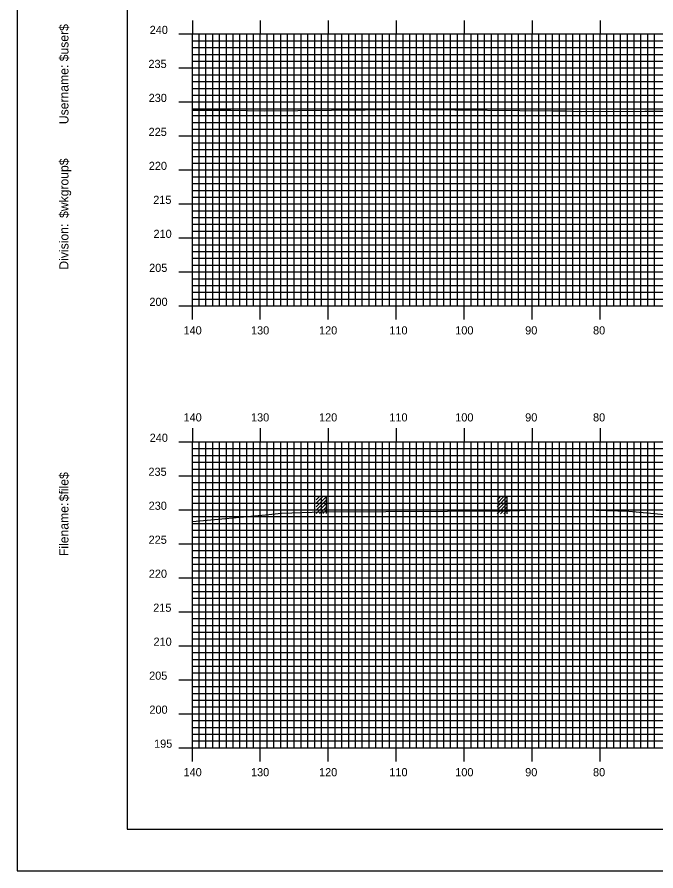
# Model space of a CAD drawing. Extents: x 1801536 to 1801879, y 442591 to 442811.
# Drawn here: x 1801535.8 to 1801629.8, y 442590.5 to 442716.2 of the extents above; entities that cross this region are included whole.
import ezdxf

# ---------------------------------------------------------------- set-up
doc = ezdxf.new("R2010")
doc.units = 0
for name, color, linetype in [('BORDER', 7, 'Continuous'), ('H_V ANNOTATION', 7, 'Continuous'), ('M_Buildings_Rooftop', 7, 'Continuous'), ('MAJOR', 7, 'Continuous'), ('MINOR', 7, 'Continuous'), ('PLOT BOUNDARY', 7, 'Continuous'), ('S_Roadway_Centerline', 7, 'Continuous')]:
    doc.layers.add(name, color=color, linetype=linetype)

msp = doc.modelspace()

# ---------------------------------------------------------------- linework, layer by layer
at = {"layer": 'BORDER'}
msp.add_lwpolyline([(1801551.98, 442596.67), (1801871.98, 442596.67), (1801871.98, 442806.67), (1801551.98, 442806.67)], close=True, dxfattribs=at)
at = {"layer": 'M_Buildings_Rooftop'}
for p, q in [((1801579.81, 442644.13), (1801581.32, 442645.64)), ((1801579.81, 442644.63), (1801580.8, 442645.64)), ((1801579.81, 442645.12), (1801580.3, 442645.64)), ((1801579.81, 442643.64), (1801581.32, 442645.12)), ((1801579.81, 442643.12), (1801581.32, 442644.63)), ((1801581.32, 442643.12), (1801581.32, 442645.64)), ((1801606.41, 442644.1), (1801607.92, 442645.61)), ((1801606.41, 442644.59), (1801607.4, 442645.61)), ((1801606.41, 442645.09), (1801606.91, 442645.61)), ((1801606.41, 442643.61), (1801607.92, 442645.09)), ((1801606.41, 442643.09), (1801607.92, 442644.59)), ((1801607.92, 442643.09), (1801607.92, 442645.61)), ((1801580.3, 442643.12), (1801581.32, 442644.13)), ((1801580.8, 442643.12), (1801581.32, 442643.64)), ((1801606.91, 442643.09), (1801607.92, 442644.1)), ((1801607.4, 442643.09), (1801607.92, 442643.61))]:
    msp.add_line(p, q, dxfattribs=at)
at = {"layer": 'MAJOR'}
for p, q in [((1801561.58, 442715.67), (1801561.58, 442713.67)), ((1801571.58, 442715.67), (1801571.58, 442713.67)), ((1801581.58, 442715.67), (1801581.58, 442713.67)), ((1801591.58, 442715.67), (1801591.58, 442713.67)), ((1801601.58, 442715.67), (1801601.58, 442713.67)), ((1801611.58, 442715.67), (1801611.58, 442713.67)), ((1801621.58, 442715.67), (1801621.58, 442713.67)), ((1801559.57, 442713.67), (1801561.58, 442713.67)), ((1801561.58, 442713.67), (1801841.58, 442713.67)), ((1801561.58, 442673.67), (1801561.58, 442713.67)), ((1801561.58, 442673.67), (1801561.58, 442713.67)), ((1801561.58, 442713.67), (1801841.58, 442713.67)), ((1801571.58, 442673.67), (1801571.58, 442713.67)), ((1801581.58, 442673.67), (1801581.58, 442713.67)), ((1801591.58, 442673.67), (1801591.58, 442713.67)), ((1801601.58, 442673.67), (1801601.58, 442713.67)), ((1801611.58, 442673.67), (1801611.58, 442713.67)), ((1801621.58, 442673.67), (1801621.58, 442713.67)), ((1801559.57, 442708.67), (1801561.58, 442708.67)), ((1801561.58, 442708.67), (1801841.58, 442708.67)), ((1801559.57, 442703.67), (1801561.58, 442703.67)), ((1801561.58, 442703.67), (1801841.58, 442703.67)), ((1801559.57, 442698.67), (1801561.58, 442698.67)), ((1801561.58, 442698.67), (1801841.58, 442698.67)), ((1801559.57, 442693.67), (1801561.58, 442693.67)), ((1801561.58, 442693.67), (1801841.58, 442693.67)), ((1801559.57, 442688.67), (1801561.58, 442688.67)), ((1801561.58, 442688.67), (1801841.58, 442688.67)), ((1801559.57, 442683.67), (1801561.58, 442683.67)), ((1801561.58, 442683.67), (1801841.58, 442683.67)), ((1801559.57, 442678.67), (1801561.58, 442678.67)), ((1801561.58, 442678.67), (1801841.58, 442678.67)), ((1801559.57, 442673.67), (1801561.58, 442673.67)), ((1801561.58, 442673.67), (1801841.58, 442673.67)), ((1801561.58, 442673.67), (1801841.58, 442673.67)), ((1801561.58, 442671.66), (1801561.58, 442673.67)), ((1801571.58, 442671.66), (1801571.58, 442673.67)), ((1801581.58, 442671.66), (1801581.58, 442673.67)), ((1801591.58, 442671.66), (1801591.58, 442673.67)), ((1801601.58, 442671.66), (1801601.58, 442673.67)), ((1801611.58, 442671.66), (1801611.58, 442673.67)), ((1801621.58, 442671.66), (1801621.58, 442673.67)), ((1801561.58, 442655.67), (1801561.58, 442653.67)), ((1801571.58, 442655.67), (1801571.58, 442653.67)), ((1801581.58, 442655.67), (1801581.58, 442653.67)), ((1801591.58, 442655.67), (1801591.58, 442653.67)), ((1801601.58, 442655.67), (1801601.58, 442653.67)), ((1801611.58, 442655.67), (1801611.58, 442653.67)), ((1801621.58, 442655.67), (1801621.58, 442653.67)), ((1801559.57, 442653.67), (1801561.58, 442653.67)), ((1801561.58, 442653.67), (1801841.58, 442653.67)), ((1801561.58, 442608.67), (1801561.58, 442653.67)), ((1801561.58, 442608.67), (1801561.58, 442653.67)), ((1801561.58, 442653.67), (1801841.58, 442653.67)), ((1801571.58, 442608.67), (1801571.58, 442653.67)), ((1801581.58, 442608.67), (1801581.58, 442653.67)), ((1801591.58, 442608.67), (1801591.58, 442653.67)), ((1801601.58, 442608.67), (1801601.58, 442653.67)), ((1801611.58, 442608.67), (1801611.58, 442653.67)), ((1801621.58, 442608.67), (1801621.58, 442653.67)), ((1801559.57, 442648.67), (1801561.58, 442648.67)), ((1801561.58, 442648.67), (1801841.58, 442648.67)), ((1801559.57, 442643.67), (1801561.58, 442643.67)), ((1801561.58, 442643.67), (1801841.58, 442643.67)), ((1801559.57, 442638.67), (1801561.58, 442638.67)), ((1801561.58, 442638.67), (1801841.58, 442638.67)), ((1801559.57, 442633.67), (1801561.58, 442633.67)), ((1801561.58, 442633.67), (1801841.58, 442633.67)), ((1801559.57, 442628.67), (1801561.58, 442628.67)), ((1801561.58, 442628.67), (1801841.58, 442628.67)), ((1801559.57, 442623.67), (1801561.58, 442623.67)), ((1801561.58, 442623.67), (1801841.58, 442623.67)), ((1801559.57, 442618.67), (1801561.58, 442618.67)), ((1801561.58, 442618.67), (1801841.58, 442618.67)), ((1801559.57, 442613.67), (1801561.58, 442613.67)), ((1801561.58, 442613.67), (1801841.58, 442613.67)), ((1801559.57, 442608.67), (1801561.58, 442608.67)), ((1801561.58, 442608.67), (1801841.58, 442608.67)), ((1801561.58, 442608.67), (1801841.58, 442608.67)), ((1801561.58, 442606.66), (1801561.58, 442608.67)), ((1801571.58, 442606.66), (1801571.58, 442608.67)), ((1801581.58, 442606.66), (1801581.58, 442608.67)), ((1801591.58, 442606.66), (1801591.58, 442608.67)), ((1801601.58, 442606.66), (1801601.58, 442608.67)), ((1801611.58, 442606.66), (1801611.58, 442608.67)), ((1801621.58, 442606.66), (1801621.58, 442608.67))]:
    msp.add_line(p, q, dxfattribs=at)
at = {"layer": 'MINOR'}
for p, q in [((1801562.58, 442673.67), (1801562.58, 442713.67)), ((1801563.58, 442673.67), (1801563.58, 442713.67)), ((1801564.58, 442673.67), (1801564.58, 442713.67)), ((1801565.58, 442673.67), (1801565.58, 442713.67)), ((1801566.58, 442673.67), (1801566.58, 442713.67)), ((1801567.58, 442673.67), (1801567.58, 442713.67)), ((1801568.58, 442673.67), (1801568.58, 442713.67)), ((1801569.58, 442673.67), (1801569.58, 442713.67)), ((1801570.58, 442673.67), (1801570.58, 442713.67)), ((1801572.58, 442673.67), (1801572.58, 442713.67)), ((1801573.58, 442673.67), (1801573.58, 442713.67)), ((1801574.58, 442673.67), (1801574.58, 442713.67)), ((1801575.58, 442673.67), (1801575.58, 442713.67)), ((1801576.58, 442673.67), (1801576.58, 442713.67)), ((1801577.58, 442673.67), (1801577.58, 442713.67)), ((1801578.58, 442673.67), (1801578.58, 442713.67)), ((1801579.58, 442673.67), (1801579.58, 442713.67)), ((1801580.58, 442673.67), (1801580.58, 442713.67)), ((1801582.58, 442673.67), (1801582.58, 442713.67)), ((1801583.58, 442673.67), (1801583.58, 442713.67)), ((1801584.58, 442673.67), (1801584.58, 442713.67)), ((1801585.58, 442673.67), (1801585.58, 442713.67)), ((1801586.58, 442673.67), (1801586.58, 442713.67)), ((1801587.58, 442673.67), (1801587.58, 442713.67)), ((1801588.58, 442673.67), (1801588.58, 442713.67)), ((1801589.58, 442673.67), (1801589.58, 442713.67)), ((1801590.58, 442673.67), (1801590.58, 442713.67)), ((1801592.58, 442673.67), (1801592.58, 442713.67)), ((1801593.58, 442673.67), (1801593.58, 442713.67)), ((1801594.58, 442673.67), (1801594.58, 442713.67)), ((1801595.58, 442673.67), (1801595.58, 442713.67)), ((1801596.58, 442673.67), (1801596.58, 442713.67)), ((1801597.58, 442673.67), (1801597.58, 442713.67)), ((1801598.58, 442673.67), (1801598.58, 442713.67)), ((1801599.58, 442673.67), (1801599.58, 442713.67)), ((1801600.58, 442673.67), (1801600.58, 442713.67)), ((1801602.58, 442673.67), (1801602.58, 442713.67)), ((1801603.58, 442673.67), (1801603.58, 442713.67)), ((1801604.58, 442673.67), (1801604.58, 442713.67)), ((1801605.58, 442673.67), (1801605.58, 442713.67)), ((1801606.58, 442673.67), (1801606.58, 442713.67)), ((1801607.58, 442673.67), (1801607.58, 442713.67)), ((1801608.58, 442673.67), (1801608.58, 442713.67)), ((1801609.58, 442673.67), (1801609.58, 442713.67)), ((1801610.58, 442673.67), (1801610.58, 442713.67)), ((1801612.58, 442673.67), (1801612.58, 442713.67)), ((1801613.58, 442673.67), (1801613.58, 442713.67)), ((1801614.58, 442673.67), (1801614.58, 442713.67)), ((1801615.58, 442673.67), (1801615.58, 442713.67)), ((1801616.58, 442673.67), (1801616.58, 442713.67)), ((1801617.58, 442673.67), (1801617.58, 442713.67)), ((1801618.58, 442673.67), (1801618.58, 442713.67)), ((1801619.58, 442673.67), (1801619.58, 442713.67)), ((1801620.58, 442673.67), (1801620.58, 442713.67)), ((1801622.58, 442673.67), (1801622.58, 442713.67)), ((1801623.58, 442673.67), (1801623.58, 442713.67)), ((1801624.58, 442673.67), (1801624.58, 442713.67)), ((1801625.58, 442673.67), (1801625.58, 442713.67)), ((1801626.58, 442673.67), (1801626.58, 442713.67)), ((1801627.58, 442673.67), (1801627.58, 442713.67)), ((1801628.58, 442673.67), (1801628.58, 442713.67)), ((1801629.58, 442673.67), (1801629.58, 442713.67)), ((1801561.58, 442712.67), (1801841.58, 442712.67)), ((1801561.58, 442712.67), (1801563.58, 442712.67)), ((1801561.58, 442711.67), (1801841.58, 442711.67)), ((1801561.58, 442711.67), (1801563.58, 442711.67)), ((1801561.58, 442710.67), (1801841.58, 442710.67)), ((1801561.58, 442710.67), (1801563.58, 442710.67)), ((1801561.58, 442709.67), (1801841.58, 442709.67)), ((1801561.58, 442709.67), (1801563.58, 442709.67)), ((1801561.58, 442707.67), (1801841.58, 442707.67)), ((1801561.58, 442707.67), (1801563.58, 442707.67)), ((1801561.58, 442706.67), (1801841.58, 442706.67)), ((1801561.58, 442706.67), (1801563.58, 442706.67)), ((1801561.58, 442705.67), (1801841.58, 442705.67)), ((1801561.58, 442705.67), (1801563.58, 442705.67)), ((1801561.58, 442704.67), (1801841.58, 442704.67)), ((1801561.58, 442704.67), (1801563.58, 442704.67)), ((1801561.58, 442702.67), (1801841.58, 442702.67)), ((1801561.58, 442702.67), (1801563.58, 442702.67)), ((1801561.58, 442701.67), (1801841.58, 442701.67)), ((1801561.58, 442701.67), (1801563.58, 442701.67)), ((1801561.58, 442700.67), (1801841.58, 442700.67)), ((1801561.58, 442700.67), (1801563.58, 442700.67)), ((1801561.58, 442699.67), (1801841.58, 442699.67)), ((1801561.58, 442699.67), (1801563.58, 442699.67)), ((1801561.58, 442697.67), (1801841.58, 442697.67)), ((1801561.58, 442697.67), (1801563.58, 442697.67)), ((1801561.58, 442696.67), (1801841.58, 442696.67)), ((1801561.58, 442696.67), (1801563.58, 442696.67)), ((1801561.58, 442695.67), (1801841.58, 442695.67)), ((1801561.58, 442695.67), (1801563.58, 442695.67)), ((1801561.58, 442694.67), (1801841.58, 442694.67)), ((1801561.58, 442694.67), (1801563.58, 442694.67)), ((1801561.58, 442692.67), (1801841.58, 442692.67)), ((1801561.58, 442692.67), (1801563.58, 442692.67)), ((1801561.58, 442691.67), (1801841.58, 442691.67)), ((1801561.58, 442691.67), (1801563.58, 442691.67)), ((1801561.58, 442690.67), (1801841.58, 442690.67)), ((1801561.58, 442690.67), (1801563.58, 442690.67)), ((1801561.58, 442689.67), (1801841.58, 442689.67)), ((1801561.58, 442689.67), (1801563.58, 442689.67)), ((1801561.58, 442687.67), (1801841.58, 442687.67)), ((1801561.58, 442687.67), (1801563.58, 442687.67)), ((1801561.58, 442686.67), (1801841.58, 442686.67)), ((1801561.58, 442686.67), (1801563.58, 442686.67)), ((1801561.58, 442685.67), (1801841.58, 442685.67)), ((1801561.58, 442685.67), (1801563.58, 442685.67)), ((1801561.58, 442684.67), (1801841.58, 442684.67)), ((1801561.58, 442684.67), (1801563.58, 442684.67)), ((1801561.58, 442682.67), (1801841.58, 442682.67)), ((1801561.58, 442682.67), (1801563.58, 442682.67)), ((1801561.58, 442681.67), (1801841.58, 442681.67)), ((1801561.58, 442681.67), (1801563.58, 442681.67)), ((1801561.58, 442680.67), (1801841.58, 442680.67)), ((1801561.58, 442680.67), (1801563.58, 442680.67)), ((1801561.58, 442679.67), (1801841.58, 442679.67)), ((1801561.58, 442679.67), (1801563.58, 442679.67)), ((1801561.58, 442677.67), (1801841.58, 442677.67)), ((1801561.58, 442677.67), (1801563.58, 442677.67)), ((1801561.58, 442676.67), (1801841.58, 442676.67)), ((1801561.58, 442676.67), (1801563.58, 442676.67)), ((1801561.58, 442675.67), (1801841.58, 442675.67)), ((1801561.58, 442675.67), (1801563.58, 442675.67)), ((1801561.58, 442674.67), (1801841.58, 442674.67)), ((1801561.58, 442674.67), (1801563.58, 442674.67)), ((1801562.58, 442608.67), (1801562.58, 442653.67)), ((1801563.58, 442608.67), (1801563.58, 442653.67)), ((1801564.58, 442608.67), (1801564.58, 442653.67)), ((1801565.58, 442608.67), (1801565.58, 442653.67)), ((1801566.58, 442608.67), (1801566.58, 442653.67)), ((1801567.58, 442608.67), (1801567.58, 442653.67)), ((1801568.58, 442608.67), (1801568.58, 442653.67)), ((1801569.58, 442608.67), (1801569.58, 442653.67)), ((1801570.58, 442608.67), (1801570.58, 442653.67)), ((1801572.58, 442608.67), (1801572.58, 442653.67)), ((1801573.58, 442608.67), (1801573.58, 442653.67)), ((1801574.58, 442608.67), (1801574.58, 442653.67)), ((1801575.58, 442608.67), (1801575.58, 442653.67)), ((1801576.58, 442608.67), (1801576.58, 442653.67)), ((1801577.58, 442608.67), (1801577.58, 442653.67)), ((1801578.58, 442608.67), (1801578.58, 442653.67)), ((1801579.58, 442608.67), (1801579.58, 442653.67)), ((1801580.58, 442608.67), (1801580.58, 442653.67)), ((1801582.58, 442608.67), (1801582.58, 442653.67)), ((1801583.58, 442608.67), (1801583.58, 442653.67)), ((1801584.58, 442608.67), (1801584.58, 442653.67)), ((1801585.58, 442608.67), (1801585.58, 442653.67)), ((1801586.58, 442608.67), (1801586.58, 442653.67)), ((1801587.58, 442608.67), (1801587.58, 442653.67)), ((1801588.58, 442608.67), (1801588.58, 442653.67)), ((1801589.58, 442608.67), (1801589.58, 442653.67)), ((1801590.58, 442608.67), (1801590.58, 442653.67)), ((1801592.58, 442608.67), (1801592.58, 442653.67)), ((1801593.58, 442608.67), (1801593.58, 442653.67)), ((1801594.58, 442608.67), (1801594.58, 442653.67)), ((1801595.58, 442608.67), (1801595.58, 442653.67)), ((1801596.58, 442608.67), (1801596.58, 442653.67)), ((1801597.58, 442608.67), (1801597.58, 442653.67)), ((1801598.58, 442608.67), (1801598.58, 442653.67)), ((1801599.58, 442608.67), (1801599.58, 442653.67)), ((1801600.58, 442608.67), (1801600.58, 442653.67)), ((1801602.58, 442608.67), (1801602.58, 442653.67)), ((1801603.58, 442608.67), (1801603.58, 442653.67)), ((1801604.58, 442608.67), (1801604.58, 442653.67)), ((1801605.58, 442608.67), (1801605.58, 442653.67)), ((1801606.58, 442608.67), (1801606.58, 442653.67)), ((1801607.58, 442608.67), (1801607.58, 442653.67)), ((1801608.58, 442608.67), (1801608.58, 442653.67)), ((1801609.58, 442608.67), (1801609.58, 442653.67)), ((1801610.58, 442608.67), (1801610.58, 442653.67)), ((1801612.58, 442608.67), (1801612.58, 442653.67)), ((1801613.58, 442608.67), (1801613.58, 442653.67)), ((1801614.58, 442608.67), (1801614.58, 442653.67)), ((1801615.58, 442608.67), (1801615.58, 442653.67)), ((1801616.58, 442608.67), (1801616.58, 442653.67)), ((1801617.58, 442608.67), (1801617.58, 442653.67)), ((1801618.58, 442608.67), (1801618.58, 442653.67)), ((1801619.58, 442608.67), (1801619.58, 442653.67)), ((1801620.58, 442608.67), (1801620.58, 442653.67)), ((1801622.58, 442608.67), (1801622.58, 442653.67)), ((1801623.58, 442608.67), (1801623.58, 442653.67)), ((1801624.58, 442608.67), (1801624.58, 442653.67)), ((1801625.58, 442608.67), (1801625.58, 442653.67)), ((1801626.58, 442608.67), (1801626.58, 442653.67)), ((1801627.58, 442608.67), (1801627.58, 442653.67)), ((1801628.58, 442608.67), (1801628.58, 442653.67)), ((1801629.58, 442608.67), (1801629.58, 442653.67)), ((1801561.58, 442652.67), (1801841.58, 442652.67)), ((1801561.58, 442652.67), (1801563.58, 442652.67)), ((1801561.58, 442651.67), (1801841.58, 442651.67)), ((1801561.58, 442651.67), (1801563.58, 442651.67)), ((1801561.58, 442650.67), (1801841.58, 442650.67)), ((1801561.58, 442650.67), (1801563.58, 442650.67)), ((1801561.58, 442649.67), (1801841.58, 442649.67)), ((1801561.58, 442649.67), (1801563.58, 442649.67)), ((1801561.58, 442647.67), (1801841.58, 442647.67)), ((1801561.58, 442647.67), (1801563.58, 442647.67)), ((1801561.58, 442646.67), (1801841.58, 442646.67)), ((1801561.58, 442646.67), (1801563.58, 442646.67)), ((1801561.58, 442645.67), (1801841.58, 442645.67)), ((1801561.58, 442645.67), (1801563.58, 442645.67)), ((1801561.58, 442644.67), (1801841.58, 442644.67)), ((1801561.58, 442644.67), (1801563.58, 442644.67)), ((1801561.58, 442642.67), (1801841.58, 442642.67)), ((1801561.58, 442642.67), (1801563.58, 442642.67)), ((1801561.58, 442641.67), (1801841.58, 442641.67)), ((1801561.58, 442641.67), (1801563.58, 442641.67)), ((1801561.58, 442640.67), (1801841.58, 442640.67)), ((1801561.58, 442640.67), (1801563.58, 442640.67)), ((1801561.58, 442639.67), (1801841.58, 442639.67)), ((1801561.58, 442639.67), (1801563.58, 442639.67)), ((1801561.58, 442637.67), (1801841.58, 442637.67)), ((1801561.58, 442637.67), (1801563.58, 442637.67)), ((1801561.58, 442636.67), (1801841.58, 442636.67)), ((1801561.58, 442636.67), (1801563.58, 442636.67)), ((1801561.58, 442635.67), (1801841.58, 442635.67)), ((1801561.58, 442635.67), (1801563.58, 442635.67)), ((1801561.58, 442634.67), (1801841.58, 442634.67)), ((1801561.58, 442634.67), (1801563.58, 442634.67)), ((1801561.58, 442632.67), (1801841.58, 442632.67)), ((1801561.58, 442632.67), (1801563.58, 442632.67)), ((1801561.58, 442631.67), (1801841.58, 442631.67)), ((1801561.58, 442631.67), (1801563.58, 442631.67)), ((1801561.58, 442630.67), (1801841.58, 442630.67)), ((1801561.58, 442630.67), (1801563.58, 442630.67)), ((1801561.58, 442629.67), (1801841.58, 442629.67)), ((1801561.58, 442629.67), (1801563.58, 442629.67)), ((1801561.58, 442627.67), (1801841.58, 442627.67)), ((1801561.58, 442627.67), (1801563.58, 442627.67)), ((1801561.58, 442626.67), (1801841.58, 442626.67)), ((1801561.58, 442626.67), (1801563.58, 442626.67)), ((1801561.58, 442625.67), (1801841.58, 442625.67)), ((1801561.58, 442625.67), (1801563.58, 442625.67)), ((1801561.58, 442624.67), (1801841.58, 442624.67)), ((1801561.58, 442624.67), (1801563.58, 442624.67)), ((1801561.58, 442622.67), (1801841.58, 442622.67)), ((1801561.58, 442622.67), (1801563.58, 442622.67)), ((1801561.58, 442621.67), (1801841.58, 442621.67)), ((1801561.58, 442621.67), (1801563.58, 442621.67)), ((1801561.58, 442620.67), (1801841.58, 442620.67)), ((1801561.58, 442620.67), (1801563.58, 442620.67)), ((1801561.58, 442619.67), (1801841.58, 442619.67)), ((1801561.58, 442619.67), (1801563.58, 442619.67)), ((1801561.58, 442617.67), (1801841.58, 442617.67)), ((1801561.58, 442617.67), (1801563.58, 442617.67)), ((1801561.58, 442616.67), (1801841.58, 442616.67)), ((1801561.58, 442616.67), (1801563.58, 442616.67)), ((1801561.58, 442615.67), (1801841.58, 442615.67)), ((1801561.58, 442615.67), (1801563.58, 442615.67)), ((1801561.58, 442614.67), (1801841.58, 442614.67)), ((1801561.58, 442614.67), (1801563.58, 442614.67)), ((1801561.58, 442612.67), (1801841.58, 442612.67)), ((1801561.58, 442612.67), (1801563.58, 442612.67)), ((1801561.58, 442611.67), (1801841.58, 442611.67)), ((1801561.58, 442611.67), (1801563.58, 442611.67)), ((1801561.58, 442610.67), (1801841.58, 442610.67)), ((1801561.58, 442610.67), (1801563.58, 442610.67)), ((1801561.58, 442609.67), (1801841.58, 442609.67)), ((1801561.58, 442609.67), (1801563.58, 442609.67))]:
    msp.add_line(p, q, dxfattribs=at)
at = {"layer": 'PLOT BOUNDARY'}
msp.add_lwpolyline([(1801535.79, 442590.55), (1801875.79, 442590.55), (1801875.79, 442810.55), (1801535.79, 442810.55)], close=True, dxfattribs=at)
at = {"layer": 'S_Roadway_Centerline'}
for points in [[(1801561.58, 442702.44), (1801567.26, 442702.44), (1801572.14, 442702.38), (1801587.01, 442702.53), (1801594.18, 442702.6), (1801595.37, 442702.54), (1801614.57, 442702.35), (1801616.44, 442702.39), (1801618.79, 442702.29), (1801628.17, 442702.34), (1801635.49, 442702.32)], [(1801561.58, 442641.93), (1801572.35, 442642.94), (1801574.7, 442643.19), (1801580.72, 442643.38), (1801580.73, 442643.38), (1801580.96, 442643.38), (1801608.19, 442643.53), (1801608.3, 442643.53), (1801609.78, 442643.57), (1801611.8, 442643.72), (1801612.37, 442643.66), (1801620.96, 442643.61), (1801625.82, 442643.48), (1801633.2, 442642.77)]]:
    msp.add_lwpolyline(points, dxfattribs=at)

# ---------------------------------------------------------------- texts
at = {"layer": 'BORDER'}
for s, p in [('$user$', (1801543.35, 442709.65)), ('Username:', (1801543.35, 442700.4)), ('$wkgroup$', (1801543.35, 442686.6)), ('Division:', (1801543.35, 442679)), ('$file$', (1801543.35, 442644.92)), ('Filename:', (1801543.35, 442636.86))]:
    msp.add_text(s, height=1.339, rotation=90, dxfattribs=at).set_placement(p)
at = {"layer": 'H_V ANNOTATION'}
for s, p in [('240', (1801555.3, 442713.67)), ('235', (1801555.12, 442708.67)), ('230', (1801555.15, 442703.67)), ('225', (1801555.14, 442698.67)), ('220', (1801555.17, 442693.67)), ('215', (1801555.82, 442688.67)), ('210', (1801555.86, 442683.67)), ('205', (1801555.22, 442678.67)), ('200', (1801555.26, 442673.67)), ('140', (1801560.28, 442669.47)), ('130', (1801570.21, 442669.47)), ('120', (1801580.22, 442669.47)), ('110', (1801590.56, 442669.47)), ('100', (1801600.26, 442669.47)), ('90', (1801610.55, 442669.47)), ('80', (1801620.53, 442669.47)), ('140', (1801560.28, 442656.67)), ('130', (1801570.21, 442656.67)), ('120', (1801580.22, 442656.67)), ('110', (1801590.56, 442656.67)), ('100', (1801600.26, 442656.67)), ('90', (1801610.55, 442656.67)), ('80', (1801620.53, 442656.67)), ('240', (1801555.3, 442653.67)), ('235', (1801555.12, 442648.67)), ('230', (1801555.15, 442643.67)), ('225', (1801555.14, 442638.67)), ('220', (1801555.17, 442633.67)), ('215', (1801555.82, 442628.67)), ('210', (1801555.86, 442623.67)), ('205', (1801555.22, 442618.67)), ('200', (1801555.26, 442613.67)), ('195', (1801555.95, 442608.67)), ('140', (1801560.28, 442604.47)), ('130', (1801570.21, 442604.47)), ('120', (1801580.22, 442604.47)), ('110', (1801590.56, 442604.47)), ('100', (1801600.26, 442604.47)), ('90', (1801610.55, 442604.47)), ('80', (1801620.53, 442604.47))]:
    msp.add_text(s, height=1.2, dxfattribs=at).set_placement(p)
at = {"layer": 'MAJOR'}
for p in [(1801561.57, 442673.67), (1801561.57, 442608.67)]:
    msp.add_text('-', height=0.012, dxfattribs=at).set_placement(p)

doc.saveas('drawing.dxf')
